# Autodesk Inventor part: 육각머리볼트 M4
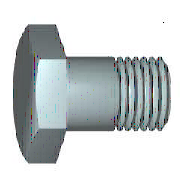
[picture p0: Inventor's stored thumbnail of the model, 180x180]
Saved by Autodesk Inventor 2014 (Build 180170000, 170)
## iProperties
IsCustomPart: 1
Created: 2012-02
Part Number: 육각머리볼트 M4
Material: 강철, 연강
Description: 6각 머리 볼트 및 6각 머리 나사
Document SubType Name: Modeling
Standard: KS B 1002
Designer: mduedu
Standards Organization: KS
Language: ko-KR
Size Designation: A + B M4 x 16
Categories: <MemberInstance><Categories><Category DisplayName="조임쇠" InternalName="e4da775c-781d-43d5-af7c-5136215cf5a6" Mnemonic="FSTN"><Category DisplayName="볼트" InternalN
Density: 1 g/cm^3
Appearance: Steel
Author: mduedu
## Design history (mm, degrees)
sketch "스케치1"
  geometry: L1 (0, 2.94)-(0, 2); L2 (2.1, 2)-(16, 2); L3 (16, 2)-(16, 0); L4 (16, 0)-(-0.4, 0); L5 (-3.68, 0)-(19.28, 0) reference; L6 (-0.4, 0)-(-0.4, 2.94); L7 (-0.4, 2.94)-(0, 2.94); L8 (2.1, 2)-(1.67, 2); L9 (1.67, 2)-(0, 2); L10 (0, -0.588)-(0, 3.528) reference
  constraints: 16 end point, 2 collinear, 2 perpendicular, 1 parallel
  dimensions: "d0" = 16 distance between parallel lines of L3 L1 (= NLG); "d1" = 13.9 distance from line of L2.start L3 (= GEL); "d2" = 4 diameter of L2 L4 (= GD); "d9" = 0.4001 distance between parallel lines of L6 L1 (computed from SD); "d10" = 5.88 diameter of L7 L4 (= SD2); "d13" = 0.42952 distance of L2.start L8.end (computed from GAL); "d14" = 4 diameter of L9 L4 (= BDM)
revolve "본체" sketch "스케치1" stored, may be unused: angle "d12" = 90 deg
sketch "스케치2"
  geometry: L1 (0, 4.041)-(3.5, 2.021); L2 (3.5, 2.021)-(3.5, -2.021); L3 (3.5, -2.021)-(0, -4.041); L4 (0, -4.041)-(-3.5, -2.021); L5 (-3.5, -2.021)-(-3.5, 2.021); L6 (-3.5, 2.021)-(0, 4.041); 2 further points
  constraints: 12 end point, 1 coincident, 1 vertical, 11 other
  dimensions: "d11" = 7 distance between parallel lines of L5 L2 (= SW)
extrude "머리" join sketch "스케치2" distance "d3" = 2.4 (= KOH - SD); taper "d4" = 0 deg
sketch "스케치4"
  geometry: L1 (-2.8, 3.5)-(-2.8, 4.041); L2 (-2.8, 4.041)-(-2.487, 4.041); L3 (-2.487, 4.041)-(-2.8, 3.5); L4 (-3.28, 0)-(0.08, 0) reference; L5 (-0.4, 4.041)-(-2.8, 4.041) reference; L6 (-2.8, 2.021)-(-2.8, 4.041) reference
  constraints: 6 end point, 2 collinear, 1 perpendicular, 1 vertical
  dimensions: "d5" = 30 deg angle of L3 L1 (= ANG1); "d19" = 7 diameter of L1.start L4 (= SW0)
revolve "모따기1" sketch "스케치4" stored, may be unused: angle "d21" = 90 deg
workplane "Work Plane1"
body "Solid1"
feature "스레드" dims "d15" = 13.9 (= GEL), "d16" = 0
chamfer "모따기2" distance "d6" = 0.42941 (= -0.5 x SPD + 0.5 x GD); stored, may be unused: second distance "d7" = 0.42952 (computed from GUL), angle "d55" = 45 deg
other parameters: "NLG" = 16 [user parameter; used in 1 equation term], "GD" = 4 (= NND) [user parameter; used in 2 equation terms], "BDM" = 4 (= NND) [user parameter; used in 1 equation term], "KOH" = 2.8 [user parameter; used in 1 equation term], "GEL" = 13.9 [user parameter; used in 2 equation terms], "SW" = 7 [user parameter; used in 3 equation terms], "SW0" = 7 (= SW) [user parameter; used in 1 equation term], "SPD" = 3.14117 (= NND - 1.2269 x PTC) [user parameter; used in 1 equation term], "SD2" = 5.88 (= SDH) [user parameter; used in 1 equation term], "SD" = 0.4 [user parameter; used in 2 equation terms], "ANG1" = 30 deg [user parameter; used in 1 equation term], "GAL" = 0.42941 (= 0.61345 x PTC) [user parameter; used in 1 equation term], "GUL" = 0.42941 (= 0.61345 x PTC) [user parameter; used in 1 equation term], "d8" = 0, "RR" = 0.2 [user parameter], "d57" = 0, "d58" = 0, "TPU" = 14.28571 (computed from PTC) [user parameter], "GD1" = 3.14117 (= THREADDIA - 1.2269 x PTC) [user parameter], "THREADDIA" = 4 [user parameter; used in 1 equation term], "SDH" = 5.88 [user parameter; used in 1 equation term], "SDHG" = 2.1 [user parameter], "TOA" = 30 deg [user parameter], "PTC" = 0.7 [user parameter; used in 5 equation terms], "NND" = 4 [user parameter; used in 3 equation terms], "E0" = 8.085 (= 1.155 x SW) [user parameter]
